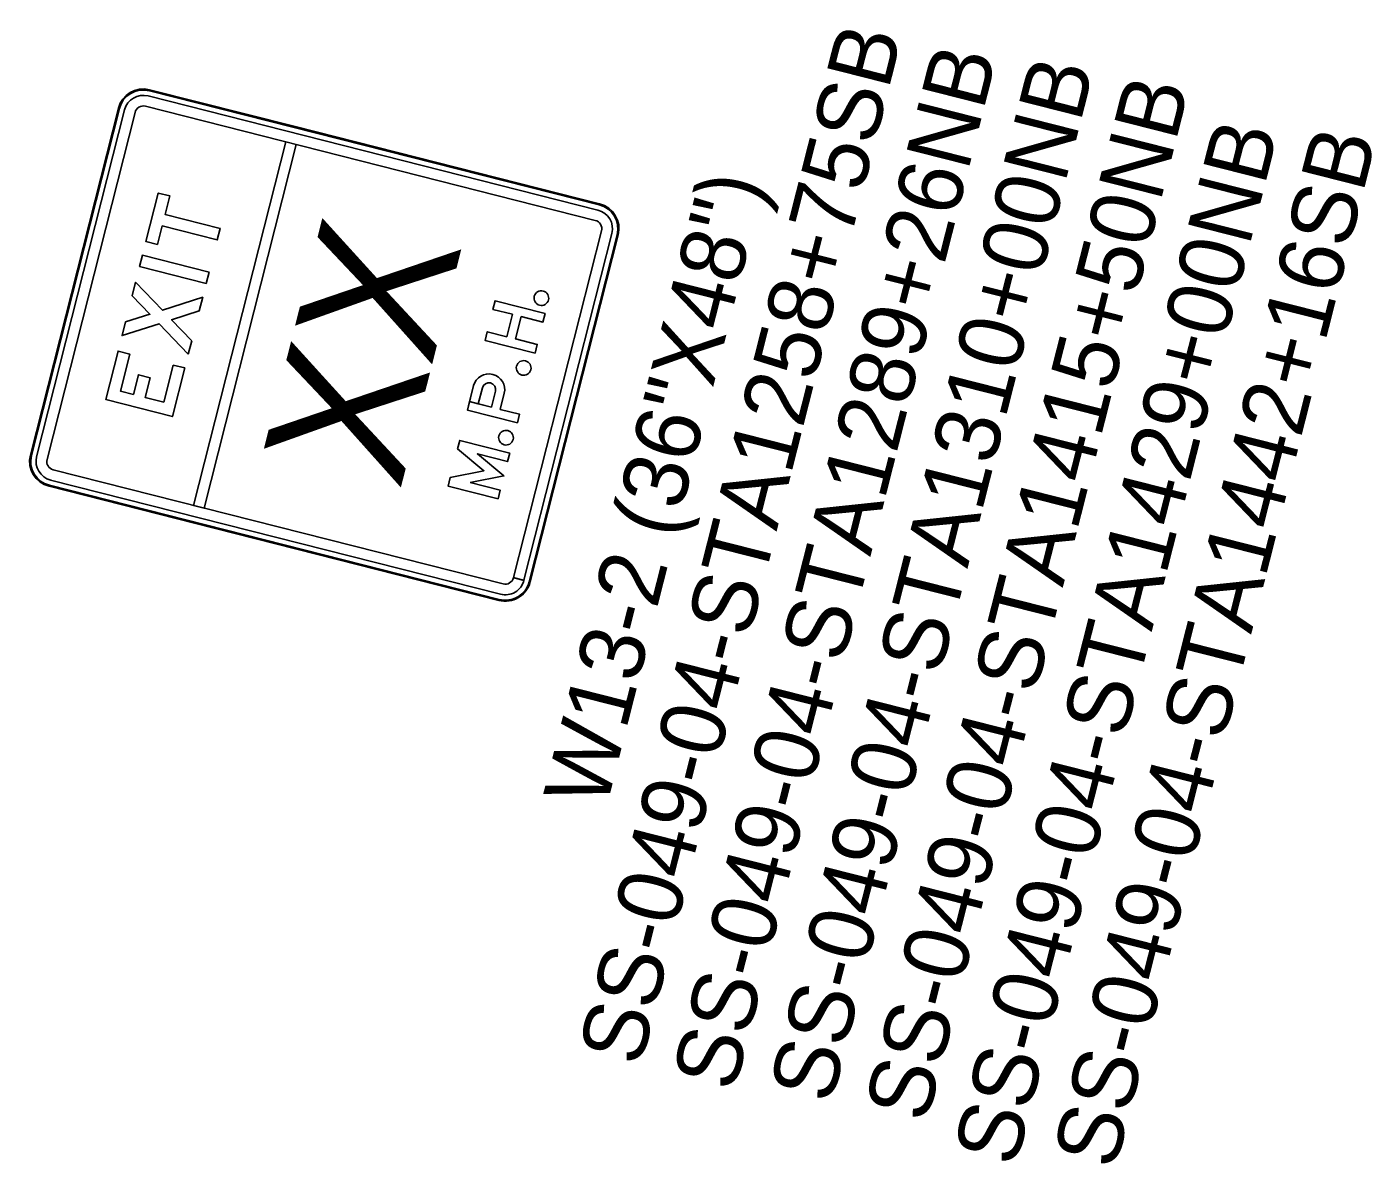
# Model space of a CAD drawing. Extents: x 670257 to 671518, y 737783 to 738188.
# Drawn here: x 670256.82 to 670262.02, y 738127.56 to 738131.95 of the extents above; entities that cross this region are included whole.
import ezdxf

# ---------------------------------------------------------------- set-up
doc = ezdxf.new("R2010")
doc.units = 0
doc.layers.add('GSCOLORFILL', color=7, linetype='Continuous')
doc.layers.add('R_SIGN_ANNOT', color=7, linetype='Continuous')

msp = doc.modelspace()

# ---------------------------------------------------------------- linework, layer by layer
at = {"layer": 'GSCOLORFILL'}
for p, q in [((670259.0256, 738131.2415), (670257.2876, 738131.6823)), ((670257.2927, 738131.7023), (670257.2927, 738131.7023)), ((670259.0307, 738131.2615), (670257.2927, 738131.7023)), ((670257.8559, 738131.5637), (670257.2937, 738131.7063)), ((670259.0317, 738131.2655), (670257.2937, 738131.7063)), ((670257.1729, 738131.635), (670256.8329, 738130.2945)), ((670257.1729, 738131.635), (670256.8329, 738130.2945)), ((670257.1769, 738131.634), (670256.837, 738130.2935)), ((670257.197, 738131.6289), (670256.857, 738130.2884)), ((670257.2372, 738131.6187), (670256.8973, 738130.2782)), ((670257.1769, 738131.634), (670257.1769, 738131.634)), ((670259.0155, 738131.2016), (670257.2775, 738131.6424)), ((670259.0317, 738131.2655), (670257.8559, 738131.5637)), ((670257.8196, 738131.5049), (670257.4635, 738130.1006)), ((670257.8196, 738131.5049), (670257.4635, 738130.1006)), ((670257.8196, 738131.5049), (670257.4635, 738130.1006)), ((670257.5037, 738130.0904), (670257.8599, 738131.4947)), ((670257.5037, 738130.0904), (670257.8599, 738131.4947)), ((670257.5037, 738130.0904), (670257.8599, 738131.4947)), ((670257.8599, 738131.4947), (670257.8196, 738131.5049)), ((670257.8599, 738131.4947), (670257.8196, 738131.5049)), ((670257.8599, 738131.4947), (670257.8196, 738131.5049)), ((670259.0307, 738131.2615), (670259.0307, 738131.2615)), ((670258.6997, 738129.8215), (670259.0396, 738131.1616)), ((670258.7399, 738129.8113), (670259.0798, 738131.1514)), ((670258.76, 738129.8058), (670259.1, 738131.1463)), ((670258.764, 738129.8047), (670259.104, 738131.1452)), ((670258.764, 738129.8048), (670259.104, 738131.1452)), ((670259.0999, 738131.1463), (670259.1, 738131.1463)), ((670258.6299, 738130.5423), (670258.6142, 738130.4801)), ((670258.648, 738130.4715), (670258.6637, 738130.5336)), ((670256.8369, 738130.2935), (670256.837, 738130.2935)), ((670256.9214, 738130.2381), (670258.6593, 738129.7973)), ((670256.9052, 738130.1743), (670257.4674, 738130.0317)), ((670256.9052, 738130.1743), (670258.6431, 738129.7335)), ((670256.9062, 738130.1782), (670256.9062, 738130.1783)), ((670256.9062, 738130.1782), (670258.6441, 738129.7374)), ((670256.9112, 738130.1982), (670258.6492, 738129.7574)), ((670257.4635, 738130.1006), (670257.5037, 738130.0904)), ((670257.4635, 738130.1006), (670257.5037, 738130.0904)), ((670257.4635, 738130.1006), (670257.5037, 738130.0904)), ((670257.4674, 738130.0317), (670258.6431, 738129.7335)), ((670258.7398, 738129.8109), (670258.6996, 738129.8211)), ((670258.6997, 738129.8215), (670258.7399, 738129.8113)), ((670258.764, 738129.8047), (670258.76, 738129.8058)), ((670258.76, 738129.8058), (670258.76, 738129.8058)), ((670258.76, 738129.8058), (670258.764, 738129.8048)), ((670258.6442, 738129.7375), (670258.6441, 738129.7374))]:
    msp.add_line(p, q, dxfattribs=at)
for points in [[(670257.3244, 738131.1084), (670257.3426, 738131.1801), (670257.555, 738131.1262), (670257.5662, 738131.1702), (670257.3537, 738131.2241), (670257.3719, 738131.2958), (670257.3269, 738131.3072), (670257.2793, 738131.1199)], [(670257.3244, 738131.1084), (670257.3426, 738131.1801), (670257.555, 738131.1262), (670257.5662, 738131.1702), (670257.3537, 738131.2241), (670257.3719, 738131.2958), (670257.3269, 738131.3072), (670257.2793, 738131.1199)], [(670257.3244, 738131.1084), (670257.3426, 738131.1801), (670257.555, 738131.1262), (670257.5662, 738131.1702), (670257.3537, 738131.2241), (670257.3719, 738131.2958), (670257.3269, 738131.3072), (670257.2793, 738131.1199)], [(670257.5122, 738130.9575), (670257.2547, 738131.0228), (670257.2659, 738131.0668), (670257.5234, 738131.0015)], [(670257.5122, 738130.9575), (670257.2547, 738131.0228), (670257.2659, 738131.0668), (670257.5234, 738131.0015)], [(670257.5122, 738130.9575), (670257.2547, 738131.0228), (670257.2659, 738131.0668), (670257.5234, 738131.0015)], [(670257.4429, 738130.6844), (670257.4562, 738130.7366), (670257.3783, 738130.8179), (670257.4855, 738130.8522), (670257.4988, 738130.9045), (670257.3431, 738130.8546), (670257.2395, 738130.9627), (670257.2262, 738130.9104), (670257.2946, 738130.8391), (670257.2005, 738130.809), (670257.1873, 738130.7568), (670257.3298, 738130.8024)], [(670257.4429, 738130.6844), (670257.4562, 738130.7366), (670257.3783, 738130.8179), (670257.4855, 738130.8522), (670257.4988, 738130.9045), (670257.3431, 738130.8546), (670257.2395, 738130.9627), (670257.2262, 738130.9104), (670257.2946, 738130.8391), (670257.2005, 738130.809), (670257.1873, 738130.7568), (670257.3298, 738130.8024)], [(670257.4429, 738130.6844), (670257.4562, 738130.7366), (670257.3783, 738130.8179), (670257.4855, 738130.8522), (670257.4988, 738130.9045), (670257.3431, 738130.8546), (670257.2395, 738130.9627), (670257.2262, 738130.9104), (670257.2946, 738130.8391), (670257.2005, 738130.809), (670257.1873, 738130.7568), (670257.3298, 738130.8024)], [(670258.6956, 738130.8387), (670258.6736, 738130.752), (670258.5981, 738130.7711), (670258.5897, 738130.7381), (670258.7828, 738130.6891), (670258.7912, 738130.7222), (670258.7074, 738130.7434), (670258.7294, 738130.8302), (670258.8132, 738130.8089), (670258.8216, 738130.8419), (670258.6285, 738130.8909), (670258.6201, 738130.8579)], [(670258.6956, 738130.8387), (670258.6736, 738130.752), (670258.5981, 738130.7711), (670258.5897, 738130.7381), (670258.7828, 738130.6891), (670258.7912, 738130.7222), (670258.7074, 738130.7434), (670258.7294, 738130.8302), (670258.8132, 738130.8089), (670258.8216, 738130.8419), (670258.6285, 738130.8909), (670258.6201, 738130.8579)], [(670258.6956, 738130.8387), (670258.6736, 738130.752), (670258.5981, 738130.7711), (670258.5897, 738130.7381), (670258.7828, 738130.6891), (670258.7912, 738130.7222), (670258.7074, 738130.7434), (670258.7294, 738130.8302), (670258.8132, 738130.8089), (670258.8216, 738130.8419), (670258.6285, 738130.8909), (670258.6201, 738130.8579)], [(670257.3844, 738130.6428), (670257.3481, 738130.4994), (670257.2762, 738130.5176), (670257.2955, 738130.5936), (670257.2504, 738130.605), (670257.2312, 738130.5291), (670257.1807, 738130.5419), (670257.2171, 738130.6852), (670257.172, 738130.6967), (670257.1245, 738130.5092), (670257.3819, 738130.4439), (670257.4295, 738130.6314)], [(670257.3844, 738130.6428), (670257.3481, 738130.4994), (670257.2762, 738130.5176), (670257.2955, 738130.5936), (670257.2504, 738130.605), (670257.2312, 738130.5291), (670257.1807, 738130.5419), (670257.2171, 738130.6852), (670257.172, 738130.6967), (670257.1245, 738130.5092), (670257.3819, 738130.4439), (670257.4295, 738130.6314)], [(670257.3844, 738130.6428), (670257.3481, 738130.4994), (670257.2762, 738130.5176), (670257.2955, 738130.5936), (670257.2504, 738130.605), (670257.2312, 738130.5291), (670257.1807, 738130.5419), (670257.2171, 738130.6852), (670257.172, 738130.6967), (670257.1245, 738130.5092), (670257.3819, 738130.4439), (670257.4295, 738130.6314)], [(670258.5321, 738130.1889), (670258.6624, 738130.2145), (670258.5601, 738130.2992), (670258.6764, 738130.2697), (670258.6848, 738130.3027), (670258.4917, 738130.3517), (670258.4833, 738130.3184), (670258.5851, 738130.2341), (670258.4554, 738130.2086), (670258.447, 738130.1753), (670258.6401, 738130.1263), (670258.6485, 738130.1593)], [(670258.5321, 738130.1889), (670258.6624, 738130.2145), (670258.5601, 738130.2992), (670258.6764, 738130.2697), (670258.6848, 738130.3027), (670258.4917, 738130.3517), (670258.4833, 738130.3184), (670258.5851, 738130.2341), (670258.4554, 738130.2086), (670258.447, 738130.1753), (670258.6401, 738130.1263), (670258.6485, 738130.1593)], [(670258.5321, 738130.1889), (670258.6624, 738130.2145), (670258.5601, 738130.2992), (670258.6764, 738130.2697), (670258.6848, 738130.3027), (670258.4917, 738130.3517), (670258.4833, 738130.3184), (670258.5851, 738130.2341), (670258.4554, 738130.2086), (670258.447, 738130.1753), (670258.6401, 738130.1263), (670258.6485, 738130.1593)]]:
    msp.add_lwpolyline(points, close=True, dxfattribs=at)
for points in [[(670258.5454, 738130.5635), (670258.5213, 738130.4685), (670258.7144, 738130.4195), (670258.7228, 738130.4525), (670258.648, 738130.4715)], [(670258.5297, 738130.5015), (670258.5213, 738130.4685), (670258.7144, 738130.4195), (670258.7228, 738130.4525), (670258.648, 738130.4715), (670258.6637, 738130.5336)], [(670258.5297, 738130.5015), (670258.5213, 738130.4685), (670258.7144, 738130.4195), (670258.7228, 738130.4525), (670258.648, 738130.4715), (670258.6637, 738130.5336)], [(670258.5454, 738130.5635), (670258.5297, 738130.5015), (670258.5635, 738130.4929), (670258.5793, 738130.5551)], [(670258.5454, 738130.5635), (670258.5297, 738130.5015), (670258.5635, 738130.4929), (670258.5793, 738130.5551)], [(670258.6299, 738130.5423), (670258.6142, 738130.4801), (670258.5297, 738130.5015)], [(670258.6299, 738130.5423), (670258.6142, 738130.4801), (670258.5297, 738130.5015)], [(670258.6142, 738130.4801), (670258.5635, 738130.4929), (670258.5793, 738130.5551)]]:
    msp.add_lwpolyline(points, dxfattribs=at)
for centre, major_axis, ratio, start_param, end_param in [((670257.2694, 738131.6105), (-0.0966, 0.0245), 0.991667, 4.712389, 6.283185), ((670257.2694, 738131.6105), (-0.0966, 0.0245), 0.991667, 4.712389, 6.283185), ((670257.2694, 738131.6105), (-0.0925, 0.0235), 0.991667, 4.712389, 6.283185), ((670257.2694, 738131.6105), (-0.0724, 0.0184), 0.991667, 4.712389, 6.283185), ((670257.2694, 738131.6105), (-0.0322, 0.0082), 0.991667, 4.712389, 6.283185), ((670259.0074, 738131.1697), (-0.0925, 0.0235), 0.991667, 3.141593, 4.712389), ((670259.0074, 738131.1697), (-0.0966, 0.0245), 0.991667, 3.141593, 4.712389), ((670259.0074, 738131.1697), (-0.0966, 0.0245), 0.991667, 3.141593, 4.712389), ((670259.0074, 738131.1697), (-0.0322, 0.0082), 0.991667, 3.141593, 4.712389), ((670259.0074, 738131.1697), (-0.0724, 0.0184), 0.991667, 3.141593, 4.712389), ((670258.6046, 738130.5486), (-0.0591, 0.015), 0.976792, 3.141593, 6.283185), ((670258.6046, 738130.5486), (-0.0591, 0.015), 0.976792, 3.141593, 6.283185), ((670258.6046, 738130.5486), (-0.0591, 0.015), 0.976792, 3.141593, 6.283185), ((670258.6046, 738130.5487), (-0.0253, 0.0064), 0.976792, 3.141593, 6.283185), ((670258.6046, 738130.5487), (-0.0253, 0.0064), 0.976792, 3.141593, 6.283185), ((670258.6046, 738130.5487), (-0.0253, 0.0064), 0.976792, 3.141593, 6.283185), ((670256.9295, 738130.27), (-0.0966, 0.0245), 0.991667, 0, 1.570796), ((670256.9295, 738130.27), (-0.0966, 0.0245), 0.991667, 0, 1.570796), ((670256.9295, 738130.27), (-0.0925, 0.0235), 0.991667, 0, 1.570796), ((670256.9295, 738130.27), (-0.0724, 0.0184), 0.991667, 0, 1.570796), ((670256.9295, 738130.27), (-0.0322, 0.0082), 0.991667, 0, 1.570796), ((670258.6674, 738129.8292), (-0.0966, 0.0245), 0.991667, 1.570796, 3.141593), ((670258.6674, 738129.8292), (-0.0966, 0.0245), 0.991667, 1.570796, 3.141593), ((670258.6674, 738129.8292), (-0.0925, 0.0235), 0.991667, 1.570796, 3.141593), ((670258.6674, 738129.8292), (-0.0724, 0.0184), 0.991667, 1.570796, 3.141593), ((670258.6674, 738129.8292), (-0.0322, 0.0082), 0.991667, 1.570796, 3.141593)]:
    msp.add_ellipse(centre, major_axis=major_axis, ratio=ratio, start_param=start_param, end_param=end_param, dxfattribs=at)
for centre in [(670258.8072, 738130.9012), (670258.8072, 738130.9012), (670258.8072, 738130.9012), (670258.7388, 738130.6316), (670258.7388, 738130.6316), (670258.7388, 738130.6316), (670258.6705, 738130.362), (670258.6705, 738130.362), (670258.6705, 738130.362)]:
    msp.add_ellipse(centre, major_axis=(-0.0276, 0.007), ratio=0.991667, dxfattribs=at)

# ---------------------------------------------------------------- texts
msp.add_text('XX', height=0.55, rotation=75.7686, dxfattribs=at).set_placement((670258.2603, 738130.1536))
at = {"layer": 'R_SIGN_ANNOT'}
for s, p in [('SS-049-04-STA1258+75SB', (670259.1905, 738127.9273)), ('SS-049-04-STA1289+26NB', (670259.5526, 738127.8294)), ('SS-049-04-STA1310+00NB', (670259.9277, 738127.783)), ('SS-049-04-STA1415+50NB', (670260.296, 738127.7099)), ('SS-049-04-STA1429+00NB', (670260.6396, 738127.5394)), ('SS-049-04-STA1442+16SB', (670261.0239, 738127.5293)), ('W13-2 (36"X48")', (670259.0562, 738128.9229))]:
    msp.add_text(s, height=0.25, rotation=75.7686, dxfattribs=at).set_placement(p)

doc.saveas('drawing.dxf')
